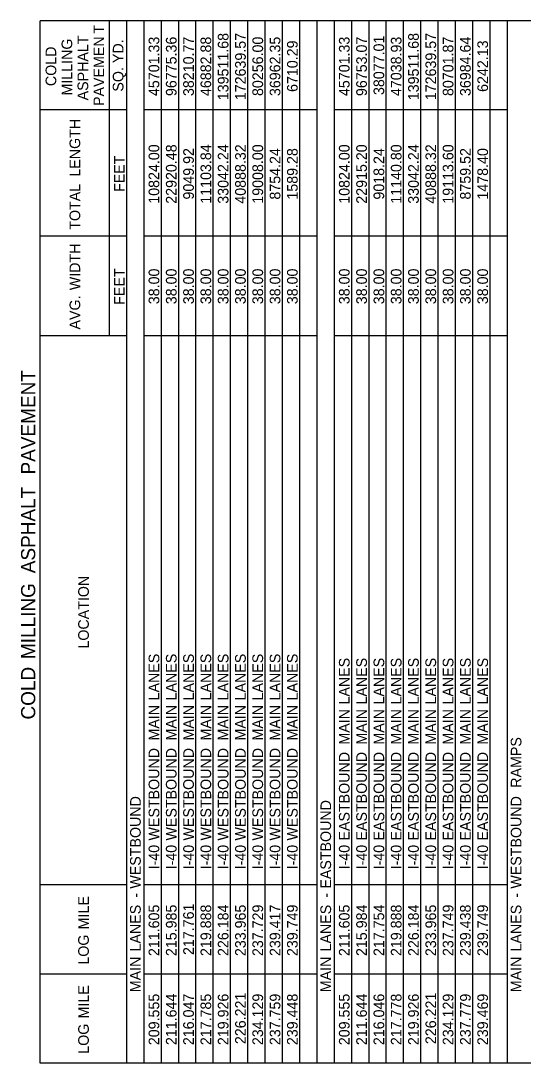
# Model space of a CAD drawing. Extents: x 2261867 to 2275370, y -3124789 to -3122260.
# Drawn here: x 2267006 to 2267289, y -3123394 to -3122807 of the extents above; entities that cross this region are included whole.
import ezdxf

# ---------------------------------------------------------------- set-up
doc = ezdxf.new("R2010")
doc.units = 0
doc.layers.add('Default', color=7, linetype='Continuous')

msp = doc.modelspace()

# ---------------------------------------------------------------- linework, layer by layer
at = {"layer": 'Default'}
for p, q in [((2267016.64, -3123394.26), (2267016.64, -3122806.82)), ((2268157.39, -3122806.82), (2267016.64, -3122806.82)), ((2268157.39, -3122806.82), (2267016.64, -3122806.82)), ((2267055.64, -3122984.27), (2267055.64, -3122806.82)), ((2267065.39, -3123394.26), (2267065.39, -3122806.82)), ((2267075.14, -3123394.26), (2267075.14, -3122806.82)), ((2267075.14, -3123394.26), (2267075.14, -3122806.82)), ((2267084.89, -3123394.26), (2267084.89, -3122806.82)), ((2267084.89, -3122928.21), (2267084.89, -3122806.82)), ((2267094.64, -3123344.05), (2267094.64, -3122806.82)), ((2267094.64, -3122928.21), (2267094.64, -3122806.82)), ((2267104.39, -3123344.05), (2267104.39, -3122806.82)), ((2267104.39, -3122984.27), (2267104.39, -3122806.82)), ((2267114.14, -3123344.05), (2267114.14, -3122806.82)), ((2267114.14, -3122857.03), (2267114.14, -3122806.82)), ((2267123.89, -3123344.05), (2267123.89, -3122806.82)), ((2267123.89, -3122857.03), (2267123.89, -3122806.82)), ((2267133.64, -3123394.26), (2267133.64, -3122806.82)), ((2267133.64, -3122857.03), (2267133.64, -3122806.82)), ((2267143.39, -3123344.05), (2267143.39, -3122806.82)), ((2267143.39, -3122984.27), (2267143.39, -3122806.82)), ((2267153.14, -3123344.05), (2267153.14, -3122806.82)), ((2267153.14, -3122857.03), (2267153.14, -3122806.82)), ((2267162.89, -3123344.05), (2267162.89, -3122806.82)), ((2267162.89, -3122857.03), (2267162.89, -3122806.82)), ((2267172.64, -3122928.21), (2267172.64, -3122806.82)), ((2267172.64, -3123394.26), (2267172.64, -3122806.82)), ((2267182.39, -3123394.26), (2267182.39, -3122806.82)), ((2267192.14, -3123394.26), (2267192.14, -3122806.82)), ((2267192.14, -3122928.21), (2267192.14, -3122806.82)), ((2267201.89, -3123394.26), (2267201.89, -3122806.82)), ((2267201.89, -3122857.03), (2267201.89, -3122806.82)), ((2267211.64, -3123344.05), (2267211.64, -3122806.82)), ((2267211.64, -3122984.27), (2267211.64, -3122806.82)), ((2267221.39, -3123344.05), (2267221.39, -3122806.82)), ((2267221.39, -3122984.27), (2267221.39, -3122806.82)), ((2267231.14, -3123344.05), (2267231.14, -3122806.82)), ((2267231.14, -3122984.27), (2267231.14, -3122806.82)), ((2267240.89, -3123344.05), (2267240.89, -3122806.82)), ((2267240.89, -3122857.03), (2267240.89, -3122806.82)), ((2267250.64, -3123344.05), (2267250.64, -3122806.82)), ((2267250.64, -3122857.03), (2267250.64, -3122806.82)), ((2267260.39, -3123344.05), (2267260.39, -3122806.82)), ((2267260.39, -3122857.03), (2267260.39, -3122806.82)), ((2267270.14, -3123344.05), (2267270.14, -3122806.82)), ((2267270.14, -3122857.03), (2267270.14, -3122806.82)), ((2267279.89, -3122857.03), (2267279.89, -3122806.82)), ((2267279.89, -3123394.26), (2267279.89, -3122806.82)), ((2267065.39, -3122857.03), (2267016.64, -3122857.03)), ((2267172.64, -3122857.03), (2267075.14, -3122857.03)), ((2267114.14, -3122984.27), (2267114.14, -3122857.03)), ((2267123.89, -3122984.27), (2267123.89, -3122857.03)), ((2267133.64, -3122857.03), (2267123.89, -3122857.03)), ((2267153.14, -3122984.27), (2267153.14, -3122857.03)), ((2267162.89, -3122984.27), (2267162.89, -3122857.03)), ((2267279.89, -3122857.03), (2267182.39, -3122857.03)), ((2267192.14, -3122857.03), (2267182.39, -3122857.03)), ((2267201.89, -3122928.21), (2267201.89, -3122857.03)), ((2267240.89, -3122984.27), (2267240.89, -3122857.03)), ((2267250.64, -3122984.27), (2267250.64, -3122857.03)), ((2267260.39, -3122984.27), (2267260.39, -3122857.03)), ((2267270.14, -3122984.27), (2267270.14, -3122857.03)), ((2267279.89, -3122984.27), (2267279.89, -3122857.03)), ((2267065.39, -3122928.21), (2267016.64, -3122928.21)), ((2267065.39, -3122928.21), (2267055.64, -3122928.21)), ((2267172.64, -3122928.21), (2267075.14, -3122928.21)), ((2267094.64, -3122984.27), (2267094.64, -3122928.21)), ((2267104.39, -3122928.21), (2267094.64, -3122928.21)), ((2267143.39, -3122928.21), (2267133.64, -3122928.21)), ((2267172.64, -3122984.27), (2267172.64, -3122928.21)), ((2267279.89, -3122928.21), (2267182.39, -3122928.21)), ((2267192.14, -3122928.21), (2267182.39, -3122928.21)), ((2267221.39, -3122928.21), (2267211.64, -3122928.21)), ((2267065.39, -3122984.27), (2267016.64, -3122984.27)), ((2267065.39, -3122984.27), (2267055.64, -3122984.27)), ((2267172.64, -3122984.27), (2267075.14, -3122984.27)), ((2267172.64, -3122984.27), (2267075.14, -3122984.27)), ((2267172.64, -3123293.83), (2267172.64, -3122984.27)), ((2267279.89, -3122984.27), (2267182.39, -3122984.27)), ((2267279.89, -3122984.27), (2267182.39, -3122984.27)), ((2267279.89, -3123293.83), (2267279.89, -3122984.27)), ((2267065.39, -3123293.83), (2267016.64, -3123293.83)), ((2267172.64, -3123293.83), (2267075.14, -3123293.83)), ((2267172.64, -3123293.83), (2267075.14, -3123293.83)), ((2267094.64, -3123394.26), (2267094.64, -3123293.83)), ((2267104.39, -3123394.26), (2267104.39, -3123293.83)), ((2267114.14, -3123394.26), (2267114.14, -3123293.83)), ((2267123.89, -3123394.26), (2267123.89, -3123293.83)), ((2267143.39, -3123394.26), (2267143.39, -3123293.83)), ((2267153.14, -3123394.26), (2267153.14, -3123293.83)), ((2267162.89, -3123394.26), (2267162.89, -3123293.83)), ((2267172.64, -3123394.26), (2267172.64, -3123293.83)), ((2267279.89, -3123293.83), (2267182.39, -3123293.83)), ((2267211.64, -3123394.26), (2267211.64, -3123293.83)), ((2267221.39, -3123394.26), (2267221.39, -3123293.83)), ((2267231.14, -3123394.26), (2267231.14, -3123293.83)), ((2267240.89, -3123394.26), (2267240.89, -3123293.83)), ((2267250.64, -3123394.26), (2267250.64, -3123293.83)), ((2267260.39, -3123394.26), (2267260.39, -3123293.83)), ((2267270.14, -3123394.26), (2267270.14, -3123293.83)), ((2267279.89, -3123394.26), (2267279.89, -3123293.83)), ((2267065.39, -3123344.05), (2267016.64, -3123344.05)), ((2267172.64, -3123344.05), (2267075.14, -3123344.05)), ((2267172.64, -3123344.05), (2267075.14, -3123344.05)), ((2267094.64, -3123394.26), (2267094.64, -3123344.05)), ((2267104.39, -3123394.26), (2267104.39, -3123344.05)), ((2267114.14, -3123394.26), (2267114.14, -3123344.05)), ((2267123.89, -3123394.26), (2267123.89, -3123344.05)), ((2267143.39, -3123394.26), (2267143.39, -3123344.05)), ((2267153.14, -3123394.26), (2267153.14, -3123344.05)), ((2267162.89, -3123394.26), (2267162.89, -3123344.05)), ((2267279.89, -3123344.05), (2267182.39, -3123344.05)), ((2267279.89, -3123344.05), (2267182.39, -3123344.05)), ((2267211.64, -3123394.26), (2267211.64, -3123344.05)), ((2267221.39, -3123394.26), (2267221.39, -3123344.05)), ((2267231.14, -3123394.26), (2267231.14, -3123344.05)), ((2267240.89, -3123394.26), (2267240.89, -3123344.05)), ((2267250.64, -3123394.26), (2267250.64, -3123344.05)), ((2267260.39, -3123394.26), (2267260.39, -3123344.05)), ((2267270.14, -3123394.26), (2267270.14, -3123344.05)), ((2268157.39, -3123394.26), (2267016.64, -3123394.26)), ((2268157.39, -3123394.26), (2267016.64, -3123394.26))]:
    msp.add_line(p, q, dxfattribs=at)

# ---------------------------------------------------------------- texts
for s, height, p in [('T', 6, (2267052.64, -3122814.01)), ('MILLING', 6, (2267034.64, -3122848.9)), ('ASPHALT', 6, (2267043.64, -3122851.64)), ('PAVEMEN', 6, (2267052.64, -3122854.8)), ('45701.33', 6, (2267083.69, -3122849.21)), ('96775.36', 6, (2267093.44, -3122849.21)), ('38210.77', 6, (2267103.19, -3122849.21)), ('46882.88', 6, (2267112.94, -3122849.22)), ('139511.68', 6, (2267122.69, -3122851.55)), ('172639.57', 6, (2267132.44, -3122851.54)), ('80256.00', 6, (2267142.19, -3122849.2)), ('36962.35', 6, (2267151.94, -3122849.23)), ('45701.33', 6, (2267190.94, -3122849.21)), ('96753.07', 6, (2267200.69, -3122849.21)), ('38077.01', 6, (2267210.44, -3122848.63)), ('47038.93', 6, (2267220.19, -3122849.21)), ('139511.68', 6, (2267229.94, -3122851.55)), ('172639.57', 6, (2267239.69, -3122851.54)), ('80701.87', 6, (2267249.44, -3122849.21)), ('36984.64', 6, (2267259.19, -3122849.2)), ('COLD', 6, (2267025.64, -3122843.6)), (' YD.', 6, (2267063.51, -3122832.86)), ('6710.29', 6, (2267161.69, -3122846.89)), ('6242.13', 6, (2267268.94, -3122846.88)), ('SQ.', 6, (2267063.51, -3122846.72)), (' LENGTH', 6, (2267039.14, -3122896.85)), ('10824.00', 6, (2267083.69, -3122909.89)), ('22920.48', 6, (2267093.44, -3122909.91)), ('9049.92', 6, (2267103.19, -3122907.54)), ('11103.84', 6, (2267112.94, -3122909.89)), ('33042.24', 6, (2267122.69, -3122909.89)), ('40888.32', 6, (2267132.44, -3122909.87)), ('19008.00', 6, (2267142.19, -3122909.89)), ('8754.24', 6, (2267151.94, -3122907.56)), ('1589.28', 6, (2267161.69, -3122907.58)), ('10824.00', 6, (2267190.94, -3122909.89)), ('22915.20', 6, (2267200.69, -3122909.89)), ('9018.24', 6, (2267210.44, -3122907.56)), ('11140.80', 6, (2267220.19, -3122909.89)), ('33042.24', 6, (2267229.94, -3122909.89)), ('40888.32', 6, (2267239.69, -3122909.87)), ('19113.60', 6, (2267249.44, -3122909.89)), ('8759.52', 6, (2267259.19, -3122907.54)), ('1478.40', 6, (2267268.94, -3122907.56)), ('FEET', 6, (2267064.19, -3122903.25)), ('TOTAL', 6, (2267039.14, -3122924.54)), (' WIDTH', 6, (2267039.14, -3122960.86)), ('FEET', 6, (2267064.19, -3122966.87)), ('38.00', 6, (2267083.69, -3122966.52)), ('38.00', 6, (2267093.44, -3122966.52)), ('38.00', 6, (2267103.19, -3122966.52)), ('38.00', 6, (2267112.94, -3122966.52)), ('38.00', 6, (2267122.69, -3122966.52)), ('38.00', 6, (2267132.44, -3122966.52)), ('38.00', 6, (2267142.19, -3122966.52)), ('38.00', 6, (2267151.94, -3122966.52)), ('38.00', 6, (2267161.69, -3122966.52)), ('38.00', 6, (2267190.94, -3122966.52)), ('38.00', 6, (2267200.69, -3122966.52)), ('38.00', 6, (2267210.44, -3122966.52)), ('38.00', 6, (2267220.19, -3122966.52)), ('38.00', 6, (2267229.94, -3122966.52)), ('38.00', 6, (2267239.69, -3122966.52)), ('38.00', 6, (2267249.44, -3122966.52)), ('38.00', 6, (2267259.19, -3122966.52)), ('38.00', 6, (2267268.94, -3122966.52)), ('AVG.', 6, (2267039.14, -3122980.78)), (' PAVEMENT', 8, (2267013.81, -3123065.46)), (' ASPHALT', 8, (2267013.81, -3123121.12)), ('LOCATION', 6, (2267044.01, -3123160.61)), (' MILLING', 8, (2267013.81, -3123169.49)), (' LANES', 6, (2267083.69, -3123192.04)), (' LANES', 6, (2267093.44, -3123192.04)), (' LANES', 6, (2267103.19, -3123192.04)), (' LANES', 6, (2267112.94, -3123192.04)), (' LANES', 6, (2267122.69, -3123192.04)), (' LANES', 6, (2267132.44, -3123192.04)), (' LANES', 6, (2267142.19, -3123192.04)), (' LANES', 6, (2267151.94, -3123192.04)), (' LANES', 6, (2267161.69, -3123192.04)), (' LANES', 6, (2267190.94, -3123194.36)), (' LANES', 6, (2267200.69, -3123194.36)), (' LANES', 6, (2267210.44, -3123194.36)), (' LANES', 6, (2267220.19, -3123194.36)), (' LANES', 6, (2267229.94, -3123194.36)), (' LANES', 6, (2267239.69, -3123194.36)), (' LANES', 6, (2267249.44, -3123194.36)), (' LANES', 6, (2267259.19, -3123194.36)), (' LANES', 6, (2267268.94, -3123194.36)), ('COLD', 8, (2267013.81, -3123200.61)), (' MAIN', 6, (2267083.69, -3123214.65)), (' MAIN', 6, (2267093.44, -3123214.65)), (' MAIN', 6, (2267103.19, -3123214.65)), (' MAIN', 6, (2267112.94, -3123214.65)), (' MAIN', 6, (2267122.69, -3123214.65)), (' MAIN', 6, (2267132.44, -3123214.65)), (' MAIN', 6, (2267142.19, -3123214.65)), (' MAIN', 6, (2267151.94, -3123214.65)), (' MAIN', 6, (2267161.69, -3123214.65)), (' MAIN', 6, (2267190.94, -3123216.96)), (' MAIN', 6, (2267200.69, -3123216.96)), (' MAIN', 6, (2267210.44, -3123216.96)), (' MAIN', 6, (2267220.19, -3123216.96)), (' MAIN', 6, (2267229.94, -3123216.96)), (' MAIN', 6, (2267239.69, -3123216.96)), (' MAIN', 6, (2267249.44, -3123216.96)), (' MAIN', 6, (2267259.19, -3123216.96)), (' MAIN', 6, (2267268.94, -3123216.96)), (' RAMPS', 6, (2267287.76, -3123241.27)), (' WESTBOUND', 6, (2267083.69, -3123271.02)), (' WESTBOUND', 6, (2267093.44, -3123271.02)), (' WESTBOUND', 6, (2267103.19, -3123271.02)), (' WESTBOUND', 6, (2267112.94, -3123271.02)), (' WESTBOUND', 6, (2267122.69, -3123271.02)), (' WESTBOUND', 6, (2267132.44, -3123271.02)), (' WESTBOUND', 6, (2267142.19, -3123271.02)), (' WESTBOUND', 6, (2267151.94, -3123271.02)), (' WESTBOUND', 6, (2267161.69, -3123271.02)), (' EASTBOUND', 6, (2267190.94, -3123271.02)), (' EASTBOUND', 6, (2267200.69, -3123271.02)), (' EASTBOUND', 6, (2267210.44, -3123271.02)), (' EASTBOUND', 6, (2267220.19, -3123271.02)), (' EASTBOUND', 6, (2267229.94, -3123271.02)), (' EASTBOUND', 6, (2267239.69, -3123271.02)), (' EASTBOUND', 6, (2267249.44, -3123271.02)), (' EASTBOUND', 6, (2267259.19, -3123271.02)), (' EASTBOUND', 6, (2267268.94, -3123271.02)), (' WESTBOUND', 6, (2267073.26, -3123298.14)), (' EASTBOUND', 6, (2267180.51, -3123298.14)), (' WESTBOUND', 6, (2267287.76, -3123298.14)), ('I-40', 6, (2267083.69, -3123285.06)), ('I-40', 6, (2267093.44, -3123285.06)), ('I-40', 6, (2267103.19, -3123285.06)), ('I-40', 6, (2267112.94, -3123285.06)), ('I-40', 6, (2267122.69, -3123285.06)), ('I-40', 6, (2267132.44, -3123285.06)), ('I-40', 6, (2267142.19, -3123285.06)), ('I-40', 6, (2267151.94, -3123285.06)), ('I-40', 6, (2267161.69, -3123285.06)), ('I-40', 6, (2267190.94, -3123285.06)), ('I-40', 6, (2267200.69, -3123285.06)), ('I-40', 6, (2267210.44, -3123285.06)), ('I-40', 6, (2267220.19, -3123285.06)), ('I-40', 6, (2267229.94, -3123285.06)), ('I-40', 6, (2267239.69, -3123285.06)), ('I-40', 6, (2267249.44, -3123285.06)), ('I-40', 6, (2267259.19, -3123285.06)), ('I-40', 6, (2267268.94, -3123285.06)), (' -', 6, (2267073.26, -3123303.2)), (' -', 6, (2267180.51, -3123303.2)), (' -', 6, (2267287.76, -3123303.2)), (' MILE', 6, (2267044.01, -3123321.08)), ('211.605', 6, (2267083.69, -3123333.92)), ('215.985', 6, (2267093.44, -3123333.92)), ('217.761', 6, (2267103.19, -3123333.31)), ('219.888', 6, (2267112.94, -3123333.9)), ('226.184', 6, (2267122.69, -3123333.88)), ('233.965', 6, (2267132.44, -3123333.92)), ('237.729', 6, (2267142.19, -3123333.9)), ('239.417', 6, (2267151.94, -3123333.89)), ('239.749', 6, (2267161.69, -3123333.9)), ('211.605', 6, (2267190.94, -3123333.92)), ('215.984', 6, (2267200.69, -3123333.88)), ('217.754', 6, (2267210.44, -3123333.88)), ('219.888', 6, (2267220.19, -3123333.9)), ('226.184', 6, (2267229.94, -3123333.88)), ('233.965', 6, (2267239.69, -3123333.92)), ('237.749', 6, (2267249.44, -3123333.9)), ('239.438', 6, (2267259.19, -3123333.9)), ('239.749', 6, (2267268.94, -3123333.9)), (' LANES', 6, (2267073.26, -3123333.54)), (' LANES', 6, (2267180.51, -3123333.54)), (' LANES', 6, (2267287.76, -3123333.54)), ('LOG', 6, (2267044.01, -3123338.74)), ('MAIN', 6, (2267073.26, -3123354.28)), ('MAIN', 6, (2267180.51, -3123354.28)), ('MAIN', 6, (2267287.76, -3123354.28)), (' MILE', 6, (2267044.01, -3123371.29)), ('209.555', 6, (2267083.69, -3123384.13)), ('211.644', 6, (2267093.44, -3123384.09)), ('216.047', 6, (2267103.19, -3123384.11)), ('217.785', 6, (2267112.94, -3123384.13)), ('219.926', 6, (2267122.69, -3123384.11)), ('226.221', 6, (2267132.44, -3123383.53)), ('234.129', 6, (2267142.19, -3123384.11)), ('237.759', 6, (2267151.94, -3123384.11)), ('239.448', 6, (2267161.69, -3123384.11)), ('209.555', 6, (2267190.94, -3123384.13)), ('211.644', 6, (2267200.69, -3123384.09)), ('216.046', 6, (2267210.44, -3123384.11)), ('217.778', 6, (2267220.19, -3123384.11)), ('219.926', 6, (2267229.94, -3123384.11)), ('226.221', 6, (2267239.69, -3123383.53)), ('234.129', 6, (2267249.44, -3123384.11)), ('237.779', 6, (2267259.19, -3123384.11)), ('239.469', 6, (2267268.94, -3123384.11)), ('LOG', 6, (2267044.01, -3123388.95))]:
    msp.add_text(s, height=height, rotation=90, dxfattribs=at).set_placement(p)

doc.saveas('drawing.dxf')
